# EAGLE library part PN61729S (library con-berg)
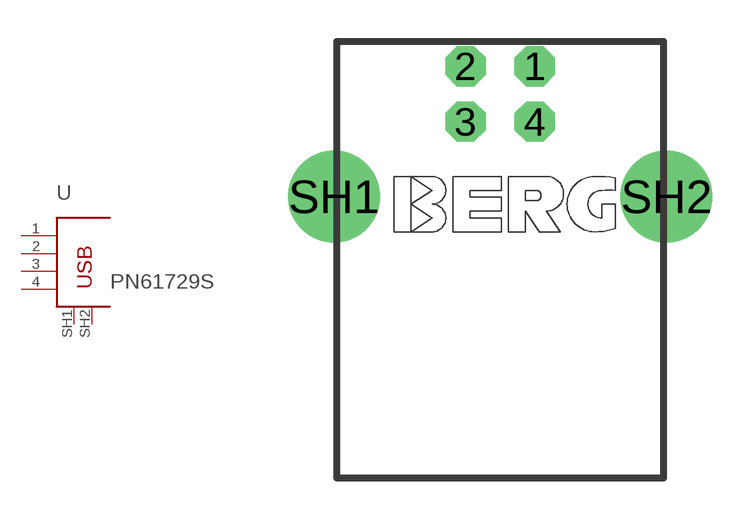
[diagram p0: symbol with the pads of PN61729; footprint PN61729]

Designator prefix -

## PN61729S  [PN61729]
1  1
2  2
3  3
4  4
SH1  SH1
SH2  SH2

## Footprint PN61729 (pad centres in mm)
BERG
drill 0.95 octagon: 1 1.25,4.71; 2 -1.25,4.71; 3 -1.25,2.71; 4 1.25,2.71
drill 2.3 round: SH1 -6,0; SH2 6,0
